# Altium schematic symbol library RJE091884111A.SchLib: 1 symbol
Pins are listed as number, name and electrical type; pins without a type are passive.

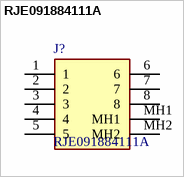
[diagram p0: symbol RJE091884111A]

## RJE091884111A
designator J?
Modular Jacks - Single port, 8P8C, R/A, shielded, Tab down, without LED; Manufacturer_Name: Amphenol Communications Solutions; Geometry.Height: 13.4mm
footprint RJE091884111A
pins: 1, 2, 3, 4, 5, 6, 7, 8, MH1, MH2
